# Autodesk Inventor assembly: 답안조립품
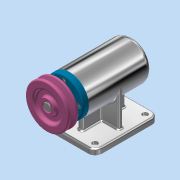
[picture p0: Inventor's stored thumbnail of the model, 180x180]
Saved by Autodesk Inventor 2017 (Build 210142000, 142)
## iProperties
Part Number: 답안조립품
Material: 일반
Document SubType Name: Assembly
Designer: mrc
Author: mrc
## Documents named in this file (12)
- C:\Users\mrc\Desktop\701004V1031\답안조립품.iam
- C:\Users\mrc\Desktop\701004V1031\본체.ipt
- C:\Users\mrc\Desktop\701004V1031\V벨트풀리.ipt
- C:\Users\mrc\Desktop\701004V1031\멈춤나사 M3.ipt
- C:\Users\mrc\Desktop\701004V1031\베어링 6004.ipt
- C:\Users\mrc\Desktop\701004V1031\베어링 51202.ipt
- C:\Users\mrc\Desktop\701004V1031\볼트 M4.ipt
- C:\Users\mrc\Desktop\701004V1031\어댑터슬리브.ipt
- C:\Users\mrc\Desktop\701004V1031\오일 실.ipt
- C:\Users\mrc\Desktop\701004V1031\축.ipt
- C:\Users\mrc\Desktop\701004V1031\커버.ipt
- C:\Users\mrc\Desktop\701004V1031\키 5 x 5 x 16.ipt
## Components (1 placed, 1 different names)
1. V벨트풀리:1
